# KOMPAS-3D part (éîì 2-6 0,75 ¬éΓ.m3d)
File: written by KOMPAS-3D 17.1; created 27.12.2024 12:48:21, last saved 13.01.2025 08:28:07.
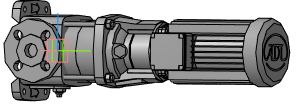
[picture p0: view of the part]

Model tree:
1. Операция без истории:4  (labels: ВМН 2-6 0,75 кВт)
